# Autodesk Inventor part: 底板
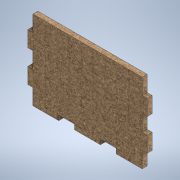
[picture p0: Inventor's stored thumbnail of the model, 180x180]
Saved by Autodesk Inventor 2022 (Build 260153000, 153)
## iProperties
Created: 2024-11
Part Number: 底板
Material: MDF 中密度繊維ボード
Document SubType Name: Modeling
Designer: shimizu
Density: 0.8 g/cm^3
Appearance: ダンボール - 段ボール紙
Author: shimizu
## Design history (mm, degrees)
sketch "スケッチ1"
  geometry: L1 (-25.119, 10.226)-(29.881, 10.226); L2 (29.881, -29.774)-(-25.119, -29.774); L3 (-25.119, 2.226)-(-27.619, 2.226); L4 (-27.619, 2.226)-(-27.619, -5.774); L5 (-27.619, -5.774)-(-25.119, -5.774); L6 (-25.119, -13.774)-(-27.619, -13.774); L7 (-27.619, -13.774)-(-27.619, -21.774); L8 (-27.619, -21.774)-(-25.119, -21.774); L9 (29.881, 2.226)-(32.381, 2.226); L10 (32.381, 2.226)-(32.381, -5.774); L11 (32.381, -5.774)-(29.881, -5.774); L12 (29.881, -13.774)-(32.381, -13.774); L13 (32.381, -13.774)-(32.381, -21.774); L14 (32.381, -21.774)-(29.881, -21.774); L15 (-25.119, 2.226)-(-25.119, 10.226); L16 (-25.119, -29.774)-(-25.119, -21.774); L17 (-25.119, -13.774)-(-25.119, -5.774); L18 (29.881, 10.226)-(29.881, 2.226); L19 (29.881, -5.774)-(29.881, -13.774); L20 (29.881, -21.774)-(29.881, -29.774); L21 (-12.119, -29.774)-(-4.119, -29.774); L22 (-4.119, -29.774)-(-4.119, -27.274); L23 (-4.119, -27.274)-(-12.119, -27.274); L24 (-12.119, -27.274)-(-12.119, -29.774); L25 (8.881, -29.774)-(16.881, -29.774); L26 (16.881, -29.774)-(16.881, -27.274); L27 (16.881, -27.274)-(8.881, -27.274); L28 (8.881, -27.274)-(8.881, -29.774); 3 further points
  constraints: 56 end point, 18 parallel, 9 perpendicular, 7 horizontal, 2 point on line
  dimensions: "d16" = 60 distance between parallel lines of L13 L7; "d17" = 8 distance between parallel lines of L22 L24; "d18" = 8 distance between parallel lines of L26 L28; "d19" = 2.5 distance of L23.end L21.start; "d20" = 2.5 distance of L25.end L26.end; "d21" = 13 distance between parallel lines of L16 L24; "d22" = 13 distance between parallel lines of L28 L22; "d23" = 13 distance between parallel lines of L20 L26
extrude "押し出し1" new body sketch "スケッチ1" distance "d2" = 2.5; taper "d3" = 0 deg
node "ソリッド1"
